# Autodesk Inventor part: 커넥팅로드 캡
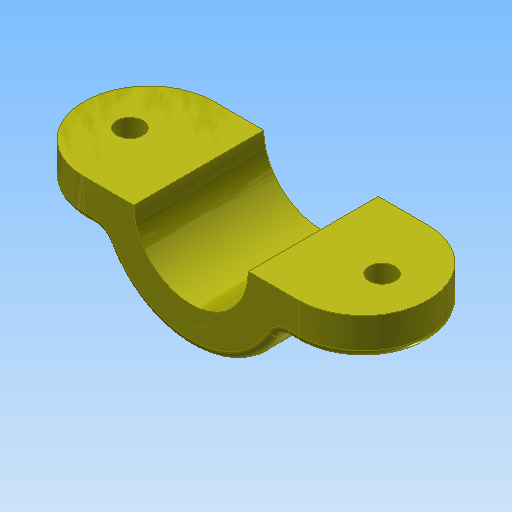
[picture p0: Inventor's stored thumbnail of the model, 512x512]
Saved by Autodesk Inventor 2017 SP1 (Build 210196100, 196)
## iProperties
Created: 2017-05
Part Number: 커넥팅로드 캡
Material: 강철, 탄소
Document SubType Name: Modeling
Designer: mduedu
Density: 7.87 g/cm^3
Mass: 31.5627 g
Surface Area: 22.8316 cm^2
Volume: 4.0105 cm^3
Appearance: 노란색
Author: mduedu
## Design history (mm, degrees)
sketch "스케치1"
  geometry: L1 (22.5, 0)-(22.5, -5); L2 (-22.5, -5)-(-22.5, 0); L3 (-22.5, 0)-(-7.5, 0); L4 (7.5, 0)-(22.5, 0); L5 (22.5, -5)-(11.456, -5); L6 (-11.456, -5)-(-22.5, -5); A1 r 7.5 centre (0, 0) between (-7.5, 0) and (7.5, 0); A2 r 12.5 centre (0, 0) between (-11.456, -5) and (11.456, -5); 2 further points
  constraints: 12 end point, 5 parallel, 4 point on circle, 3 coincident, 2 centre point, 2 collinear, 2 horizontal, 2 horizontal alignment, 2 perpendicular
  dimensions: "d0" = 45 distance of L2.end L1.start; "d2" = 5 distance of L2.start L2.end; "d3" = 15 diameter of A1; "d4" = 25 diameter of A2
extrude "돌출1" new body sketch "스케치1" stored distance "d5" = 17; taper "d6" = 0 deg
fillet "모깎기1"
fillet "모깎기2"
fillet "모깎기3" dims "d11" = 2
fillet "모깎기4" dims "d12" = 1
sketch "스케치4"
  geometry: 2 further points
  constraints: 2 other
hole "구멍1" sketch "스케치4" at (30.5, 7.5), (-2.5, 7.5) diameter "d19" = 3.4; stored, may be unused: countersink angle "d23" = 90 deg, drill point angle "d25" = 0 deg; dims "d20" = 6, "d21" = 4, "d22" = 2, "d24" = 8
node "솔리드1"
